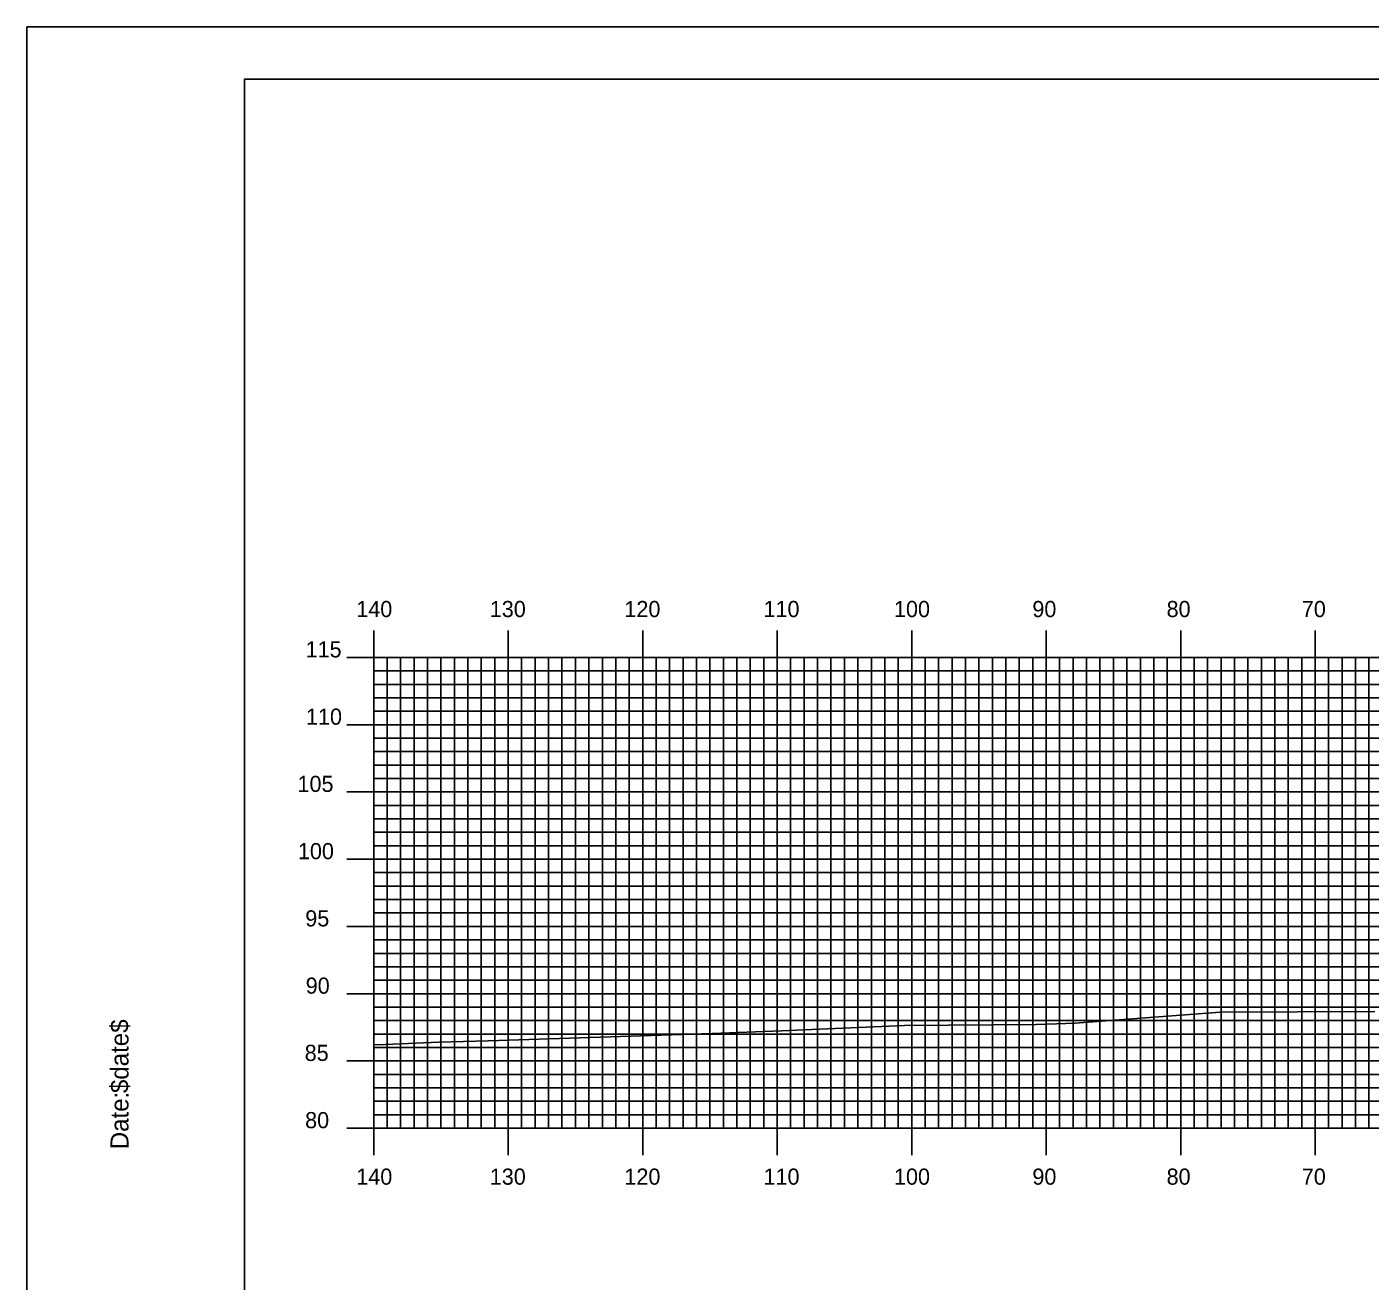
# Model space of a CAD drawing. Extents: x 1760217 to 1760560, y 442591 to 442811.
# Drawn here: x 1760216.9 to 1760316.8, y 442717.3 to 442810.5 of the extents above; entities that cross this region are included whole.
import ezdxf

# ---------------------------------------------------------------- set-up
doc = ezdxf.new("R2010")
doc.units = 0
for name, color, linetype in [('BORDER', 7, 'Continuous'), ('H_V ANNOTATION', 7, 'Continuous'), ('MAJOR', 7, 'Continuous'), ('MINOR', 7, 'Continuous'), ('PLOT BOUNDARY', 7, 'Continuous'), ('S_Roadway_Centerline', 7, 'Continuous')]:
    doc.layers.add(name, color=color, linetype=linetype)

msp = doc.modelspace()

# ---------------------------------------------------------------- linework, layer by layer
at = {"layer": 'BORDER'}
msp.add_lwpolyline([(1760233.101, 442596.665), (1760553.101, 442596.665), (1760553.101, 442806.665), (1760233.101, 442806.665)], close=True, dxfattribs=at)
at = {"layer": 'MAJOR'}
for p, q in [((1760242.701, 442765.669), (1760242.701, 442763.665)), ((1760252.701, 442765.669), (1760252.701, 442763.665)), ((1760262.701, 442765.669), (1760262.701, 442763.665)), ((1760272.701, 442765.669), (1760272.701, 442763.665)), ((1760282.701, 442765.669), (1760282.701, 442763.665)), ((1760292.701, 442765.669), (1760292.701, 442763.665)), ((1760302.701, 442765.669), (1760302.701, 442763.665)), ((1760312.701, 442765.669), (1760312.701, 442763.665)), ((1760240.697, 442763.665), (1760242.701, 442763.665)), ((1760242.701, 442763.665), (1760522.701, 442763.665)), ((1760242.701, 442728.665), (1760242.701, 442763.665)), ((1760242.701, 442728.665), (1760242.701, 442763.665)), ((1760242.701, 442763.665), (1760522.701, 442763.665)), ((1760252.701, 442728.665), (1760252.701, 442763.665)), ((1760262.701, 442728.665), (1760262.701, 442763.665)), ((1760272.701, 442728.665), (1760272.701, 442763.665)), ((1760282.701, 442728.665), (1760282.701, 442763.665)), ((1760292.701, 442728.665), (1760292.701, 442763.665)), ((1760302.701, 442728.665), (1760302.701, 442763.665)), ((1760312.701, 442728.665), (1760312.701, 442763.665)), ((1760240.697, 442758.665), (1760242.701, 442758.665)), ((1760242.701, 442758.665), (1760522.701, 442758.665)), ((1760240.697, 442753.665), (1760242.701, 442753.665)), ((1760242.701, 442753.665), (1760522.701, 442753.665)), ((1760240.697, 442748.665), (1760242.701, 442748.665)), ((1760242.701, 442748.665), (1760522.701, 442748.665)), ((1760240.697, 442743.665), (1760242.701, 442743.665)), ((1760242.701, 442743.665), (1760522.701, 442743.665)), ((1760240.697, 442738.665), (1760242.701, 442738.665)), ((1760242.701, 442738.665), (1760522.701, 442738.665)), ((1760240.697, 442733.665), (1760242.701, 442733.665)), ((1760242.701, 442733.665), (1760522.701, 442733.665)), ((1760240.697, 442728.665), (1760242.701, 442728.665)), ((1760242.701, 442728.665), (1760522.701, 442728.665)), ((1760242.701, 442728.665), (1760522.701, 442728.665)), ((1760242.701, 442726.661), (1760242.701, 442728.665)), ((1760252.701, 442726.661), (1760252.701, 442728.665)), ((1760262.701, 442726.661), (1760262.701, 442728.665)), ((1760272.701, 442726.661), (1760272.701, 442728.665)), ((1760282.701, 442726.661), (1760282.701, 442728.665)), ((1760292.701, 442726.661), (1760292.701, 442728.665)), ((1760302.701, 442726.661), (1760302.701, 442728.665)), ((1760312.701, 442726.661), (1760312.701, 442728.665))]:
    msp.add_line(p, q, dxfattribs=at)
at = {"layer": 'MINOR'}
for p, q in [((1760243.701, 442728.665), (1760243.701, 442763.665)), ((1760244.701, 442728.665), (1760244.701, 442763.665)), ((1760245.701, 442728.665), (1760245.701, 442763.665)), ((1760246.701, 442728.665), (1760246.701, 442763.665)), ((1760247.701, 442728.665), (1760247.701, 442763.665)), ((1760248.701, 442728.665), (1760248.701, 442763.665)), ((1760249.701, 442728.665), (1760249.701, 442763.665)), ((1760250.701, 442728.665), (1760250.701, 442763.665)), ((1760251.701, 442728.665), (1760251.701, 442763.665)), ((1760253.701, 442728.665), (1760253.701, 442763.665)), ((1760254.701, 442728.665), (1760254.701, 442763.665)), ((1760255.701, 442728.665), (1760255.701, 442763.665)), ((1760256.701, 442728.665), (1760256.701, 442763.665)), ((1760257.701, 442728.665), (1760257.701, 442763.665)), ((1760258.701, 442728.665), (1760258.701, 442763.665)), ((1760259.701, 442728.665), (1760259.701, 442763.665)), ((1760260.701, 442728.665), (1760260.701, 442763.665)), ((1760261.701, 442728.665), (1760261.701, 442763.665)), ((1760263.701, 442728.665), (1760263.701, 442763.665)), ((1760264.701, 442728.665), (1760264.701, 442763.665)), ((1760265.701, 442728.665), (1760265.701, 442763.665)), ((1760266.701, 442728.665), (1760266.701, 442763.665)), ((1760267.701, 442728.665), (1760267.701, 442763.665)), ((1760268.701, 442728.665), (1760268.701, 442763.665)), ((1760269.701, 442728.665), (1760269.701, 442763.665)), ((1760270.701, 442728.665), (1760270.701, 442763.665)), ((1760271.701, 442728.665), (1760271.701, 442763.665)), ((1760273.701, 442728.665), (1760273.701, 442763.665)), ((1760274.701, 442728.665), (1760274.701, 442763.665)), ((1760275.701, 442728.665), (1760275.701, 442763.665)), ((1760276.701, 442728.665), (1760276.701, 442763.665)), ((1760277.701, 442728.665), (1760277.701, 442763.665)), ((1760278.701, 442728.665), (1760278.701, 442763.665)), ((1760279.701, 442728.665), (1760279.701, 442763.665)), ((1760280.701, 442728.665), (1760280.701, 442763.665)), ((1760281.701, 442728.665), (1760281.701, 442763.665)), ((1760283.701, 442728.665), (1760283.701, 442763.665)), ((1760284.701, 442728.665), (1760284.701, 442763.665)), ((1760285.701, 442728.665), (1760285.701, 442763.665)), ((1760286.701, 442728.665), (1760286.701, 442763.665)), ((1760287.701, 442728.665), (1760287.701, 442763.665)), ((1760288.701, 442728.665), (1760288.701, 442763.665)), ((1760289.701, 442728.665), (1760289.701, 442763.665)), ((1760290.701, 442728.665), (1760290.701, 442763.665)), ((1760291.701, 442728.665), (1760291.701, 442763.665)), ((1760293.701, 442728.665), (1760293.701, 442763.665)), ((1760294.701, 442728.665), (1760294.701, 442763.665)), ((1760295.701, 442728.665), (1760295.701, 442763.665)), ((1760296.701, 442728.665), (1760296.701, 442763.665)), ((1760297.701, 442728.665), (1760297.701, 442763.665)), ((1760298.701, 442728.665), (1760298.701, 442763.665)), ((1760299.701, 442728.665), (1760299.701, 442763.665)), ((1760300.701, 442728.665), (1760300.701, 442763.665)), ((1760301.701, 442728.665), (1760301.701, 442763.665)), ((1760303.701, 442728.665), (1760303.701, 442763.665)), ((1760304.701, 442728.665), (1760304.701, 442763.665)), ((1760305.701, 442728.665), (1760305.701, 442763.665)), ((1760306.701, 442728.665), (1760306.701, 442763.665)), ((1760307.701, 442728.665), (1760307.701, 442763.665)), ((1760308.701, 442728.665), (1760308.701, 442763.665)), ((1760309.701, 442728.665), (1760309.701, 442763.665)), ((1760310.701, 442728.665), (1760310.701, 442763.665)), ((1760311.701, 442728.665), (1760311.701, 442763.665)), ((1760313.701, 442728.665), (1760313.701, 442763.665)), ((1760314.701, 442728.665), (1760314.701, 442763.665)), ((1760315.701, 442728.665), (1760315.701, 442763.665)), ((1760316.701, 442728.665), (1760316.701, 442763.665)), ((1760242.701, 442762.665), (1760522.701, 442762.665)), ((1760242.701, 442762.665), (1760244.705, 442762.665)), ((1760242.701, 442761.665), (1760522.701, 442761.665)), ((1760242.701, 442761.665), (1760244.705, 442761.665)), ((1760242.701, 442760.665), (1760522.701, 442760.665)), ((1760242.701, 442760.665), (1760244.705, 442760.665)), ((1760242.701, 442759.665), (1760522.701, 442759.665)), ((1760242.701, 442759.665), (1760244.705, 442759.665)), ((1760242.701, 442757.665), (1760522.701, 442757.665)), ((1760242.701, 442757.665), (1760244.705, 442757.665)), ((1760242.701, 442756.665), (1760522.701, 442756.665)), ((1760242.701, 442756.665), (1760244.705, 442756.665)), ((1760242.701, 442755.665), (1760522.701, 442755.665)), ((1760242.701, 442755.665), (1760244.705, 442755.665)), ((1760242.701, 442754.665), (1760522.701, 442754.665)), ((1760242.701, 442754.665), (1760244.705, 442754.665)), ((1760242.701, 442752.665), (1760522.701, 442752.665)), ((1760242.701, 442752.665), (1760244.705, 442752.665)), ((1760242.701, 442751.665), (1760522.701, 442751.665)), ((1760242.701, 442751.665), (1760244.705, 442751.665)), ((1760242.701, 442750.665), (1760522.701, 442750.665)), ((1760242.701, 442750.665), (1760244.705, 442750.665)), ((1760242.701, 442749.665), (1760522.701, 442749.665)), ((1760242.701, 442749.665), (1760244.705, 442749.665)), ((1760242.701, 442747.665), (1760522.701, 442747.665)), ((1760242.701, 442747.665), (1760244.705, 442747.665)), ((1760242.701, 442746.665), (1760522.701, 442746.665)), ((1760242.701, 442746.665), (1760244.705, 442746.665)), ((1760242.701, 442745.665), (1760522.701, 442745.665)), ((1760242.701, 442745.665), (1760244.705, 442745.665)), ((1760242.701, 442744.665), (1760522.701, 442744.665)), ((1760242.701, 442744.665), (1760244.705, 442744.665)), ((1760242.701, 442742.665), (1760522.701, 442742.665)), ((1760242.701, 442742.665), (1760244.705, 442742.665)), ((1760242.701, 442741.665), (1760522.701, 442741.665)), ((1760242.701, 442741.665), (1760244.705, 442741.665)), ((1760242.701, 442740.665), (1760522.701, 442740.665)), ((1760242.701, 442740.665), (1760244.705, 442740.665)), ((1760242.701, 442739.665), (1760522.701, 442739.665)), ((1760242.701, 442739.665), (1760244.705, 442739.665)), ((1760242.701, 442737.665), (1760522.701, 442737.665)), ((1760242.701, 442737.665), (1760244.705, 442737.665)), ((1760242.701, 442736.665), (1760522.701, 442736.665)), ((1760242.701, 442736.665), (1760244.705, 442736.665)), ((1760242.701, 442735.665), (1760522.701, 442735.665)), ((1760242.701, 442735.665), (1760244.705, 442735.665)), ((1760242.701, 442734.665), (1760522.701, 442734.665)), ((1760242.701, 442734.665), (1760244.705, 442734.665)), ((1760242.701, 442732.665), (1760522.701, 442732.665)), ((1760242.701, 442732.665), (1760244.705, 442732.665)), ((1760242.701, 442731.665), (1760522.701, 442731.665)), ((1760242.701, 442731.665), (1760244.705, 442731.665)), ((1760242.701, 442730.665), (1760522.701, 442730.665)), ((1760242.701, 442730.665), (1760244.705, 442730.665)), ((1760242.701, 442729.665), (1760522.701, 442729.665)), ((1760242.701, 442729.665), (1760244.705, 442729.665))]:
    msp.add_line(p, q, dxfattribs=at)
at = {"layer": 'PLOT BOUNDARY'}
msp.add_lwpolyline([(1760216.914, 442590.547), (1760556.914, 442590.547), (1760556.914, 442810.547), (1760216.914, 442810.547)], close=True, dxfattribs=at)
at = {"layer": 'S_Roadway_Centerline'}
msp.add_lwpolyline([(1760242.701, 442734.861), (1760243.568, 442734.892), (1760247.55, 442735.064), (1760251.205, 442735.159), (1760267.865, 442735.7), (1760273.013, 442735.91), (1760282.173, 442736.306), (1760291.949, 442736.38), (1760293.477, 442736.422), (1760294.852, 442736.475), (1760305.628, 442737.285), (1760317.142, 442737.343)], dxfattribs=at)

# ---------------------------------------------------------------- texts
at = {"layer": 'BORDER'}
for s, p in [('$date$', (1760224.471, 442731.275)), ('Date:', (1760224.471, 442727.099))]:
    msp.add_text(s, height=1.3392, rotation=90, dxfattribs=at).set_placement(p)
at = {"layer": 'H_V ANNOTATION'}
for s, p in [('140', (1760241.406, 442766.665)), ('130', (1760251.331, 442766.665)), ('120', (1760261.341, 442766.665)), ('110', (1760271.684, 442766.665)), ('100', (1760281.384, 442766.665)), ('90', (1760291.673, 442766.665)), ('80', (1760301.652, 442766.665)), ('70', (1760311.705, 442766.665)), ('115', (1760237.635, 442763.665)), ('110', (1760237.667, 442758.665)), ('105', (1760237.035, 442753.665)), ('100', (1760237.067, 442748.665)), ('95', (1760237.613, 442743.665)), ('90', (1760237.645, 442738.665)), ('85', (1760237.57, 442733.665)), ('80', (1760237.602, 442728.665)), ('140', (1760241.406, 442724.465)), ('130', (1760251.331, 442724.465)), ('120', (1760261.341, 442724.465)), ('110', (1760271.684, 442724.465)), ('100', (1760281.384, 442724.465)), ('90', (1760291.673, 442724.465)), ('80', (1760301.652, 442724.465)), ('70', (1760311.705, 442724.465))]:
    msp.add_text(s, height=1.2, dxfattribs=at).set_placement(p)
at = {"layer": 'MAJOR'}
msp.add_text('-', height=0.012, dxfattribs=at).set_placement((1760242.692, 442728.665))

doc.saveas('drawing.dxf')
